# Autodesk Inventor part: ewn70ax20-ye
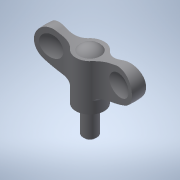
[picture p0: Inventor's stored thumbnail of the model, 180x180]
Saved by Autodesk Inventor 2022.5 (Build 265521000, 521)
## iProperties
Created: 2016-12
Part Number: ewn70ax20-ye
Material: 一般
Document SubType Name: Modeling
Designer: imaocorp
Density: 1 g/cm^3
Appearance: 既定
Author: imaocorp
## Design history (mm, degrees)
node "ewn70ax20-ye.x_t1"
node "ewn70ax20-ye"
node "Base1"
